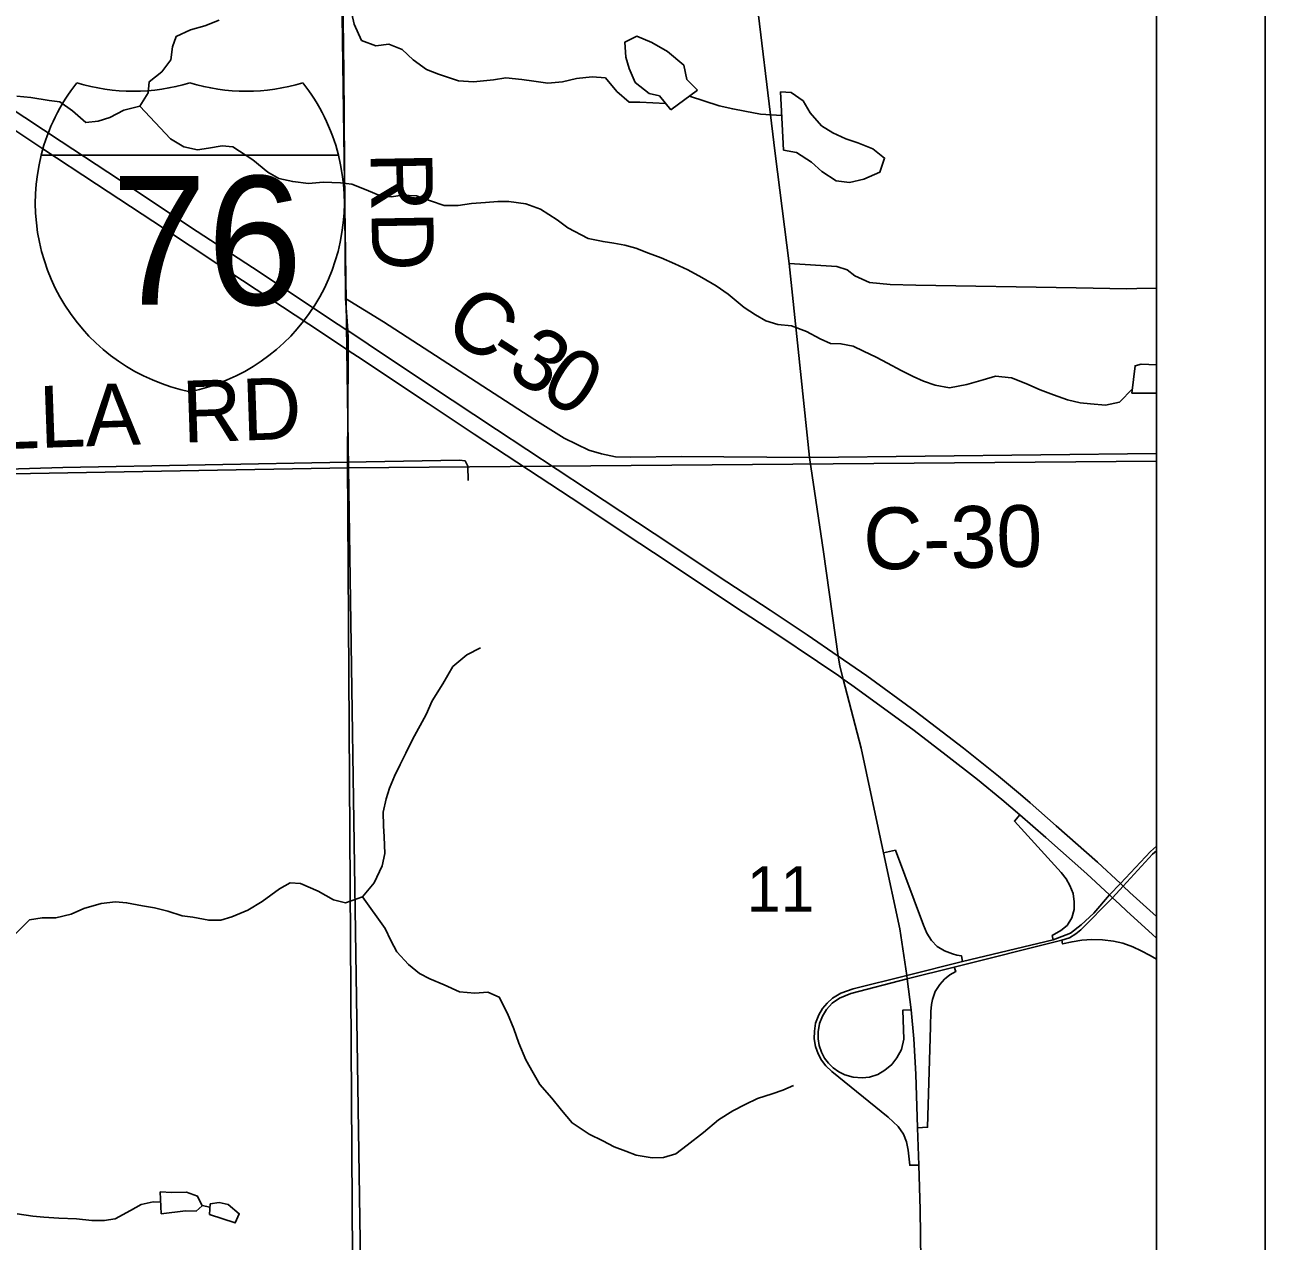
# Model space of a CAD drawing. Extents: x 0 to 36.9, y 0 to 22.
# Drawn here: x 7.859 to 9, y 18.864 to 19.983 of the extents above; entities that cross this region are included whole.
import ezdxf

# ---------------------------------------------------------------- set-up
doc = ezdxf.new("R2010")
doc.units = 0
for name, color, linetype in [('Default', 7, 'Continuous'), ('GM_X_County_Road', 7, 'Continuous'), ('GM_X_County_Road_Text', 7, 'Continuous'), ('GM_X_Interchange_Ramps', 7, 'Continuous'), ('GM_X_Interstate_Location', 7, 'Continuous'), ('GM_X_Interstate_Route', 7, 'Continuous'), ('GM_X_Interstate_Shield', 7, 'Continuous'), ('GM_X_Minor_Lake', 7, 'Continuous'), ('GM_X_Minor_River', 7, 'Continuous'), ('GM_X_Rail_Line', 7, 'Continuous'), ('GM_X_Section', 7, 'Continuous'), ('GM_X_Section_Text', 7, 'Continuous'), ('GM_X_State_Route', 7, 'Continuous'), ('GM_X_Township_Road', 7, 'Continuous'), ('GM_X_Township_Road_Text', 7, 'Continuous'), ('SH_Cut_Line', 7, 'Continuous'), ('SH_Data', 7, 'Continuous')]:
    doc.layers.add(name, color=color, linetype=linetype)

msp = doc.modelspace()

# ---------------------------------------------------------------- linework, layer by layer
at = {"layer": 'Default'}
for points in [[(8.9, 19.5814), (8.9, 20.5914), (8.452, 20.5848), (8.1429, 20.5815), (8.157, 19.5752)], [(8.9, 18.5682), (8.9, 19.5814), (8.157, 19.5752), (8.1724, 18.5598)]]:
    msp.add_lwpolyline(points, close=True, dxfattribs=at)
at = {"layer": 'GM_X_County_Road'}
msp.add_line((8.5809, 19.5847), (8.9, 19.5883), dxfattribs=at)
for points in [[(8.1453, 20.5805), (8.1466, 20.4558), (8.1498, 20.1833), (8.1528, 19.9385), (8.1544, 19.7311)], [(8.1544, 19.7311), (8.1893, 19.7095), (8.3285, 19.6193), (8.3553, 19.6025), (8.3781, 19.5916), (8.3898, 19.5881), (8.4024, 19.5854), (8.4166, 19.585), (8.4628, 19.5856), (8.5809, 19.5847)], [(8.1544, 19.7311), (8.1563, 19.7014), (8.1567, 19.6945), (8.1567, 19.6833), (8.1566, 19.6762)], [(8.1566, 19.6762), (8.1561, 19.5805), (8.1626, 18.5567), (8.1844, 17.8641), (8.1842, 17.825), (8.1824, 17.5445)], [(8.1561, 19.5805), (8.2591, 19.5822), (8.2643, 19.5816), (8.2667, 19.5768), (8.2671, 19.5635)]]:
    msp.add_lwpolyline(points, dxfattribs=at)
at = {"layer": 'GM_X_Interchange_Ramps'}
for p, q in [((8.7141, 19.1159), (8.8131, 19.1407)), ((8.8049, 19.1412), (8.7217, 19.1212))]:
    msp.add_line(p, q, dxfattribs=at)
for points in [[(8.7743, 19.2562), (8.7694, 19.2504), (8.8125, 19.203), (8.8171, 19.1971), (8.8204, 19.1912), (8.8235, 19.1837), (8.8244, 19.176), (8.8244, 19.169), (8.8222, 19.1613), (8.8178, 19.1542), (8.8121, 19.1497), (8.8042, 19.1451), (8.8049, 19.1412)], [(8.7217, 19.1212), (8.7206, 19.1265), (8.7163, 19.1271), (8.7123, 19.1281), (8.7052, 19.1309), (8.6984, 19.135), (8.6932, 19.1406), (8.689, 19.1473), (8.6857, 19.1545), (8.66, 19.2235), (8.6491, 19.2211)], [(8.9, 19.2274), (8.8946, 19.2225), (8.8668, 19.193), (8.8568, 19.1824), (8.8424, 19.1657), (8.8307, 19.1548), (8.8209, 19.1473), (8.8049, 19.1412)], [(8.8131, 19.1407), (8.8199, 19.143), (8.8258, 19.1466), (8.8306, 19.1502), (8.8595, 19.1798), (8.8695, 19.1904), (8.8963, 19.2199), (8.9, 19.2231)], [(8.8131, 19.1407), (8.8137, 19.1374), (8.8224, 19.1393), (8.8315, 19.1407), (8.8406, 19.1414), (8.8505, 19.1411), (8.8604, 19.1398), (8.8691, 19.1379), (8.8783, 19.1346), (8.886, 19.1311), (8.8941, 19.1268), (8.9, 19.1234)], [(8.7217, 19.1212), (8.6706, 19.1083), (8.621, 19.0961), (8.6098, 19.092), (8.6021, 19.0876), (8.5971, 19.0828), (8.5928, 19.0779), (8.5896, 19.0722), (8.5866, 19.0644), (8.5854, 19.0572), (8.5853, 19.05), (8.5865, 19.0431), (8.5889, 19.0362), (8.5919, 19.0303), (8.5961, 19.0251), (8.6015, 19.0201), (8.6532, 18.978), (8.6624, 18.9694), (8.6675, 18.9625), (8.6702, 18.9554), (8.6718, 18.9476), (8.6731, 18.9338), (8.6814, 18.9339)], [(8.6743, 19.0768), (8.6669, 19.0765), (8.6677, 19.0499), (8.6656, 19.0403), (8.6614, 19.0325), (8.6566, 19.0265), (8.6502, 19.0212), (8.6437, 19.0174), (8.6362, 19.0149), (8.6293, 19.0141), (8.621, 19.0147), (8.6133, 19.017), (8.608, 19.0198), (8.6026, 19.0235), (8.5983, 19.0276), (8.5947, 19.0322), (8.5919, 19.0378), (8.5899, 19.044), (8.5889, 19.0501), (8.5889, 19.0565), (8.59, 19.0643), (8.5928, 19.071), (8.5967, 19.0769), (8.6019, 19.0828), (8.6086, 19.0875), (8.619, 19.0918), (8.6709, 19.1054), (8.7141, 19.1159)], [(8.6804, 18.9683), (8.6896, 18.9687), (8.6922, 19.0612), (8.6924, 19.0751), (8.693, 19.0816), (8.6941, 19.0861), (8.6964, 19.0936), (8.7008, 19.0999), (8.7051, 19.105), (8.7101, 19.1089), (8.7154, 19.1119), (8.7141, 19.1159)]]:
    msp.add_lwpolyline(points, dxfattribs=at)
at = {"layer": 'GM_X_Interstate_Route'}
for points in [[(7.8431, 19.9082), (7.8929, 19.8754), (7.9464, 19.8401), (8.0177, 19.7927), (8.0748, 19.7554), (8.1396, 19.7124), (8.1554, 19.702)], [(7.8251, 19.9023), (7.8759, 19.8687), (7.9254, 19.8362), (7.9878, 19.795), (8.0595, 19.7475), (8.1206, 19.7073), (8.1525, 19.6861)], [(8.1554, 19.702), (8.1563, 19.7014), (8.1752, 19.6889), (8.2316, 19.6514), (8.293, 19.6104), (8.3768, 19.5553), (8.4382, 19.5149), (8.5048, 19.4704), (8.5448, 19.4443), (8.5788, 19.4216), (8.6074, 19.4019), (8.6336, 19.3839), (8.678, 19.3514), (8.7226, 19.3175), (8.7549, 19.2918), (8.7749, 19.2749), (8.784, 19.2671), (8.8079, 19.246), (8.8458, 19.2127), (8.8668, 19.193), (8.8695, 19.1904), (8.8755, 19.1848), (8.9, 19.1625)], [(8.1525, 19.6861), (8.1567, 19.6833), (8.1653, 19.6775), (8.2304, 19.6343), (8.2726, 19.6062), (8.3619, 19.5476), (8.4248, 19.5057), (8.45, 19.489), (8.5121, 19.4476), (8.5501, 19.4229), (8.5883, 19.3971), (8.6078, 19.3838)], [(8.6078, 19.3838), (8.6118, 19.381), (8.6198, 19.3755), (8.6456, 19.3567), (8.6771, 19.3336), (8.7066, 19.3109), (8.7354, 19.2886), (8.7577, 19.2701), (8.7743, 19.2562)], [(8.7743, 19.2562), (8.7983, 19.2351), (8.8361, 19.2018), (8.8568, 19.1824), (8.8595, 19.1798), (8.8659, 19.1739), (8.8728, 19.1676)], [(8.8728, 19.1676), (8.8962, 19.1464), (8.9, 19.1428)]]:
    msp.add_lwpolyline(points, dxfattribs=at)
at = {"layer": 'GM_X_Interstate_Shield'}
for p, q in [((7.8745, 19.8628), (8.1477, 19.8628)), ((8.1477, 19.8628), (7.8745, 19.8628)), ((8.1477, 19.8628), (7.8745, 19.8628))]:
    msp.add_line(p, q, dxfattribs=at)
for centre, start, end in [((8.0466, 19.8193), 141.669, 165.8066), ((7.9592, 20.0992), 253.0091, 286.9909), ((8.063, 20.0992), 253.0091, 286.9909), ((7.9756, 19.8193), 14.1934, 38.331), ((8.0466, 19.8193), 165.8066, 258.463), ((7.9756, 19.8193), 281.537, 14.1934)]:
    msp.add_arc(centre, 0.1776, start, end, dxfattribs=at)
at = {"layer": 'GM_X_Minor_Lake'}
msp.add_line((8.8774, 19.644), (8.9, 19.6438), dxfattribs=at)
for points in [[(8.4779, 19.9226), (8.4682, 19.9323), (8.4653, 19.9456), (8.4503, 19.9582), (8.4361, 19.9664), (8.4223, 19.9722), (8.411, 19.9667), (8.412, 19.9531), (8.4152, 19.9425), (8.4207, 19.9297), (8.4334, 19.9196), (8.443, 19.9175), (8.4535, 19.9044)], [(8.4535, 19.9044), (8.4779, 19.9226)], [(8.5543, 19.9212), (8.5571, 19.8673)], [(8.5571, 19.8673), (8.5689, 19.8653), (8.5827, 19.8564), (8.5924, 19.8478), (8.6055, 19.8393), (8.6177, 19.8376), (8.6309, 19.8408), (8.6456, 19.8471), (8.65, 19.8601), (8.6392, 19.8687), (8.6254, 19.8742), (8.6143, 19.8778), (8.6025, 19.8833), (8.5921, 19.8899), (8.5816, 19.9019), (8.575, 19.9128), (8.5642, 19.9206), (8.5543, 19.9212)], [(8.9, 19.67), (8.8861, 19.6707), (8.8804, 19.6691), (8.8774, 19.644)], [(7.9839, 18.9092), (7.9846, 18.8891)], [(7.9846, 18.8891), (8.007, 18.8918), (8.0169, 18.8916), (8.0225, 18.8966), (8.0182, 18.9053), (8.0079, 18.9089), (7.9946, 18.9087), (7.9839, 18.9092)], [(8.0291, 18.8884), (8.0528, 18.8808), (8.0565, 18.8892), (8.0465, 18.8978), (8.0381, 18.8995), (8.0297, 18.8982)], [(8.0297, 18.8982), (8.0291, 18.8884)]]:
    msp.add_lwpolyline(points, dxfattribs=at)
at = {"layer": 'GM_X_Minor_River'}
for points in [[(8.1519, 20.0296), (8.1623, 19.9834), (8.169, 19.9684), (8.182, 19.9633), (8.1942, 19.965), (8.2064, 19.9599), (8.2164, 19.9506), (8.2288, 19.9417), (8.2398, 19.9374), (8.2582, 19.9313), (8.2719, 19.9304), (8.2904, 19.9322), (8.3018, 19.9339), (8.3163, 19.9323), (8.3273, 19.931), (8.3402, 19.9289), (8.3539, 19.9303), (8.3667, 19.9332), (8.3811, 19.935), (8.3933, 19.934), (8.4038, 19.9213), (8.415, 19.9117), (8.4249, 19.9115), (8.4488, 19.9102)], [(7.8521, 19.9171), (7.865, 19.9158), (7.8818, 19.9131), (7.8917, 19.9118), (7.9032, 19.9036), (7.9156, 19.8928), (7.9269, 19.8942), (7.9375, 19.8974), (7.9503, 19.9041), (7.9651, 19.9078), (7.9728, 19.9201), (7.9738, 19.9303), (7.9854, 19.9396), (7.9935, 19.9504), (7.9952, 19.9626), (7.9985, 19.9721), (8.0117, 19.9781), (8.0249, 19.9817), (8.0381, 19.9869)], [(8.4705, 19.9171), (8.4978, 19.9082), (8.5104, 19.9054), (8.5214, 19.9033), (8.5359, 19.9005), (8.5555, 19.8992)], [(7.9651, 19.9078), (7.9933, 19.8779), (8.0056, 19.8705), (8.0182, 19.8677), (8.0284, 19.8694), (8.0409, 19.8715), (8.0508, 19.8706), (8.0689, 19.8584), (8.0827, 19.8472), (8.0931, 19.8414), (8.1057, 19.8385), (8.1201, 19.8369), (8.1338, 19.8379), (8.1497, 19.8374), (8.16, 19.8361), (8.1734, 19.831), (8.1872, 19.8252), (8.1967, 19.8246), (8.2065, 19.8259), (8.2194, 19.8254), (8.2324, 19.8207), (8.245, 19.8164), (8.2579, 19.8166), (8.2701, 19.8183), (8.283, 19.8193), (8.2943, 19.8203), (8.3046, 19.8201), (8.3202, 19.8181), (8.3336, 19.813), (8.3489, 19.8034), (8.3586, 19.796), (8.3773, 19.7861), (8.3911, 19.7833), (8.401, 19.782), (8.4112, 19.7799), (8.4212, 19.7774), (8.433, 19.7727), (8.4445, 19.7683), (8.4571, 19.7628), (8.469, 19.7574), (8.482, 19.7504), (8.4951, 19.7426), (8.5062, 19.7349), (8.5209, 19.7226), (8.5312, 19.716), (8.5408, 19.7104), (8.5519, 19.7072), (8.5645, 19.7059), (8.5782, 19.7005), (8.5909, 19.6939), (8.6004, 19.6895), (8.6099, 19.6893), (8.621, 19.6872), (8.6306, 19.6824), (8.6424, 19.6769), (8.6528, 19.6714), (8.6651, 19.6648), (8.6762, 19.6593), (8.6857, 19.6549), (8.6964, 19.6513), (8.7098, 19.6489), (8.7257, 19.6518), (8.7408, 19.6563), (8.7521, 19.6595), (8.7666, 19.6579), (8.7799, 19.6528), (8.793, 19.647), (8.8052, 19.6423), (8.8182, 19.6379), (8.83, 19.6351), (8.8395, 19.6341), (8.8532, 19.6329), (8.8661, 19.6357), (8.8779, 19.6478)], [(7.8499, 19.1457), (7.8637, 19.1596), (7.8754, 19.1613), (7.888, 19.1615), (7.902, 19.1648), (7.9136, 19.17), (7.9295, 19.1744), (7.9428, 19.1762), (7.953, 19.1752), (7.9675, 19.1725), (7.9786, 19.1704), (7.9908, 19.1676), (8.0041, 19.1633), (8.014, 19.1619), (8.0285, 19.1591), (8.0395, 19.1593), (8.0497, 19.1622), (8.0644, 19.1685), (8.0776, 19.1763), (8.0937, 19.188), (8.1035, 19.1935), (8.113, 19.1929), (8.129, 19.186), (8.1432, 19.1779), (8.1543, 19.1751), (8.1698, 19.1807), (8.1806, 19.1934), (8.1879, 19.2091), (8.1903, 19.2205), (8.1897, 19.2357), (8.1891, 19.2459), (8.1889, 19.2585), (8.1917, 19.2707), (8.1946, 19.2806), (8.1993, 19.2917), (8.2044, 19.3024), (8.2096, 19.3127), (8.2158, 19.3254), (8.2283, 19.3484), (8.2341, 19.361), (8.2437, 19.3767), (8.253, 19.3925), (8.2657, 19.4033), (8.2785, 19.4096)], [(8.1698, 19.1807), (8.1908, 19.1514), (8.1959, 19.1405), (8.2014, 19.13), (8.2123, 19.1184), (8.2223, 19.1102), (8.2319, 19.1051), (8.2449, 19.0996), (8.259, 19.0934), (8.2731, 19.0922), (8.2852, 19.0931), (8.2956, 19.0884), (8.3031, 19.0733), (8.309, 19.0594), (8.3138, 19.0462), (8.3201, 19.0308), (8.3268, 19.0187), (8.3331, 19.0082), (8.3439, 18.9955), (8.3529, 18.9846), (8.3626, 18.9727), (8.3783, 18.9623), (8.391, 18.9561), (8.4013, 18.9506), (8.412, 18.9466), (8.4216, 18.943), (8.4364, 18.9406), (8.4467, 18.9408), (8.458, 18.9444), (8.4685, 18.9522), (8.4835, 18.9638), (8.4973, 18.9755), (8.5105, 18.9837), (8.5218, 18.9896), (8.5331, 18.9951), (8.5466, 18.9995), (8.5565, 19.0027), (8.5663, 19.0071)], [(7.8522, 18.8891), (7.8667, 18.887), (7.8769, 18.8861), (7.8906, 18.8852), (7.907, 18.8844), (7.921, 18.8831), (7.9324, 18.8829), (7.9423, 18.8846), (7.9566, 18.8921), (7.9663, 18.8976), (7.9773, 18.9001), (7.9842, 18.8998)], [(8.0225, 18.8967), (8.0295, 18.8952)]]:
    msp.add_lwpolyline(points, dxfattribs=at)
at = {"layer": 'GM_X_Rail_Line'}
msp.add_lwpolyline([(8.9, 14.5158), (8.9, 20.5927), (8.7004, 20.5894), (8.4791, 20.5781), (8.4706, 20.5777), (8.1451, 20.581), (7.7514, 20.5725), (7.4889, 20.5693), (7.1656, 20.5637), (7.1468, 20.5633), (6.1727, 20.5478), (5.9236, 20.5446), (5.3186, 20.5329), (5.2978, 20.5324), (5.1496, 20.5295), (4.5929, 20.5183), (4.1742, 20.5119), (4.2095, 19.5156), (4.2124, 19.4314), (4.22, 18.531), (4.2174, 18.4382), (4.2214, 17.442), (4.2237, 16.806), (4.2428, 16.065)], dxfattribs=at)
at = {"layer": 'GM_X_Section'}
for points in [[(8.1429, 20.5815), (8.157, 19.5752), (7.1591, 19.5574), (7.1483, 20.5676), (7.9531, 20.5791)], [(8.157, 19.5752), (8.1724, 18.5598), (7.173, 18.5435), (7.1591, 19.5574)]]:
    msp.add_lwpolyline(points, close=True, dxfattribs=at)
at = {"layer": 'GM_X_State_Route'}
for points in [[(8.6082, 19.3968), (8.6074, 19.4019), (8.5937, 19.4979), (8.5809, 19.5847), (8.5704, 19.6843), (8.5621, 19.7633), (8.5494, 19.8642), (8.5296, 20.0295), (8.5094, 20.1975), (8.4969, 20.3096), (8.4932, 20.3393)], [(8.6814, 18.9339), (8.6804, 18.9683), (8.6788, 19.0175), (8.6768, 19.05), (8.6743, 19.0768), (8.6709, 19.1054), (8.6706, 19.1083), (8.6641, 19.1513), (8.6491, 19.2211), (8.6285, 19.3173), (8.6118, 19.381), (8.6088, 19.3927), (8.6082, 19.3968)], [(8.689, 18.5531), (8.6887, 18.5631), (8.688, 18.62), (8.6839, 18.799), (8.6827, 18.8932), (8.6814, 18.9339)]]:
    msp.add_lwpolyline(points, dxfattribs=at)
at = {"layer": 'GM_X_Township_Road'}
msp.add_line((8.9, 19.7406), (8.8819, 19.7402), dxfattribs=at)
for points in [[(8.8819, 19.7402), (8.8727, 19.74), (8.8261, 19.7407), (8.6788, 19.7432), (8.6552, 19.7439), (8.6361, 19.7457), (8.6226, 19.7519), (8.6157, 19.7575), (8.6061, 19.7603), (8.5621, 19.7633)], [(7.6186, 19.5672), (7.8942, 19.5757), (8.1561, 19.5805)]]:
    msp.add_lwpolyline(points, dxfattribs=at)
at = {"layer": 'SH_Cut_Line'}
msp.add_lwpolyline([(8.9, 14.5158), (8.9, 20.9), (2.1, 20.9), (2.1, 14.4405)], dxfattribs=at)
at = {"layer": 'SH_Data'}
for p, q in [((9, 21), (9, 14)), ((8.9, 20.9), (8.9, 14.1))]:
    msp.add_line(p, q, dxfattribs=at)

# ---------------------------------------------------------------- texts
at = {"layer": 'GM_X_County_Road_Text'}
for s, height, rotation, p in [('RD', 0.05682, 270.9872, (8.1772, 19.8656)), ('C', 0.0568, 327.2619, (8.2423, 19.6994)), ('3', 0.0568, 327.3098, (8.3007, 19.6618)), ('-', 0.0568, 327.2637, (8.2812, 19.6744)), ('0', 0.0568, 328.4395, (8.331, 19.6424)), ('C-30', 0.05682, 1.0286, (8.6308, 19.4815))]:
    msp.add_text(s, height=height, rotation=rotation, dxfattribs=at).set_placement(p)
at = {"layer": 'GM_X_Interstate_Location'}
for s in ['.', '-', ',']:
    msp.add_text(s, height=0.000189, dxfattribs=at).set_placement((8.0111, 19.7872))
msp.add_text('76', height=0.000189, rotation=0, dxfattribs=at).set_placement((7.9724, 19.748))
at = {"layer": 'GM_X_Interstate_Shield'}
msp.add_text('76', height=0.11837, dxfattribs=at).set_placement((7.9388, 19.7252))
at = {"layer": 'GM_X_Section_Text'}
msp.add_text('11', height=0.04186, rotation=0, dxfattribs=at).set_placement((8.5232, 19.167))
at = {"layer": 'GM_X_Township_Road_Text'}
for s, rotation, p in [('RD', 1.9757, (8.0049, 19.5984)), ('CALLA', 1.9891, (7.7258, 19.5884))]:
    msp.add_text(s, height=0.05682, rotation=rotation, dxfattribs=at).set_placement(p)

doc.saveas('drawing.dxf')
